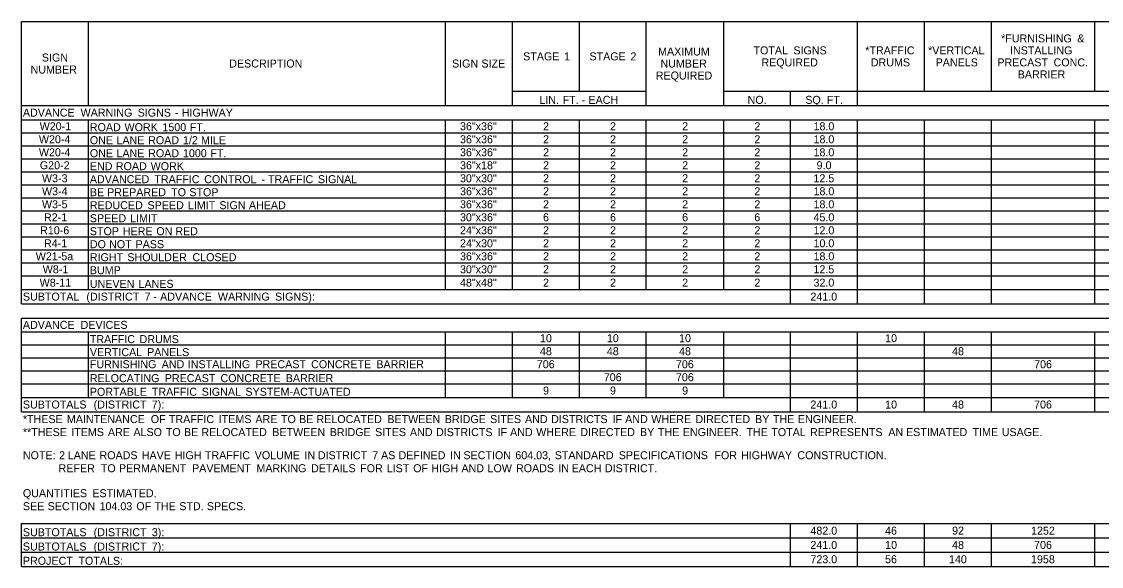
# Model space of a CAD drawing. Extents: x 544478 to 1930787, y -1948294 to 596640.
# Drawn here: x 544484 to 545294, y -1946942 to -1946533 of the extents above; entities that cross this region are included whole.
import ezdxf

# ---------------------------------------------------------------- set-up
doc = ezdxf.new("R2010")
doc.units = 0
doc.layers.add('Default', color=7, linetype='Continuous')

msp = doc.modelspace()

# ---------------------------------------------------------------- linework, layer by layer
at = {"layer": 'Default'}
for p, q in [((544484.28, -1946533.34), (545456.84, -1946533.34)), ((544484.28, -1946744.91), (544484.28, -1946533.34)), ((544484.28, -1946744.91), (544484.28, -1946533.34)), ((544534.49, -1946596.22), (544534.49, -1946533.34)), ((544802.13, -1946596.22), (544802.13, -1946533.34)), ((544852.34, -1946596.22), (544852.34, -1946533.34)), ((544902.55, -1946585.5), (544902.55, -1946533.34)), ((544952.76, -1946596.22), (544952.76, -1946533.34)), ((545010.78, -1946596.22), (545010.78, -1946533.34)), ((545111.2, -1946596.22), (545111.2, -1946533.34)), ((545161.41, -1946585.5), (545161.41, -1946533.34)), ((545211.63, -1946585.5), (545211.63, -1946533.34)), ((545289.14, -1946585.5), (545289.14, -1946533.34)), ((544852.34, -1946585.5), (544952.76, -1946585.5)), ((544952.76, -1946596.22), (544952.76, -1946585.5)), ((545010.78, -1946585.5), (545456.84, -1946585.5)), ((545060.99, -1946596.22), (545060.99, -1946585.5)), ((545111.2, -1946596.22), (545111.2, -1946585.5)), ((544484.28, -1946596.22), (545456.84, -1946596.22)), ((544952.76, -1946596.22), (545456.84, -1946596.22)), ((544484.28, -1946606.95), (545456.84, -1946606.95)), ((544534.49, -1946694.7), (544534.49, -1946606.95)), ((544534.49, -1946734.19), (544534.49, -1946606.95)), ((544802.13, -1946694.7), (544802.13, -1946606.95)), ((544802.13, -1946734.19), (544802.13, -1946606.95)), ((544852.34, -1946694.7), (544852.34, -1946606.95)), ((544852.34, -1946734.19), (544852.34, -1946606.95)), ((544902.55, -1946684.95), (544902.55, -1946606.95)), ((544902.55, -1946734.19), (544902.55, -1946606.95)), ((544952.76, -1946694.7), (544952.76, -1946606.95)), ((544952.76, -1946734.19), (544952.76, -1946606.95)), ((545010.78, -1946734.19), (545010.78, -1946606.95)), ((545060.99, -1946694.7), (545060.99, -1946606.95)), ((545060.99, -1946744.91), (545060.99, -1946606.95)), ((545111.2, -1946694.7), (545111.2, -1946606.95)), ((545111.2, -1946744.91), (545111.2, -1946606.95)), ((545161.41, -1946694.7), (545161.41, -1946606.95)), ((545161.41, -1946744.91), (545161.41, -1946606.95)), ((545211.63, -1946694.7), (545211.63, -1946606.95)), ((545211.63, -1946744.91), (545211.63, -1946606.95)), ((545289.14, -1946694.7), (545289.14, -1946606.95)), ((545289.14, -1946744.91), (545289.14, -1946606.95)), ((544484.28, -1946616.7), (545456.84, -1946616.7)), ((544484.28, -1946626.45), (545456.84, -1946626.45)), ((544484.28, -1946636.2), (545456.84, -1946636.2)), ((544484.28, -1946645.95), (545456.84, -1946645.95)), ((544484.28, -1946655.7), (545456.84, -1946655.7)), ((544484.28, -1946665.45), (545456.84, -1946665.45)), ((544484.28, -1946675.2), (545456.84, -1946675.2)), ((544484.28, -1946684.95), (545456.84, -1946684.95)), ((544484.28, -1946694.7), (545456.84, -1946694.7)), ((544484.28, -1946704.45), (545456.84, -1946704.45)), ((544484.28, -1946714.2), (545456.84, -1946714.2)), ((544484.28, -1946723.95), (545456.84, -1946723.95)), ((544484.28, -1946734.19), (545456.84, -1946734.19)), ((544484.28, -1946734.19), (545456.84, -1946734.19)), ((545111.2, -1946744.91), (545111.2, -1946734.19)), ((545161.41, -1946744.91), (545161.41, -1946734.19)), ((545211.63, -1946744.91), (545211.63, -1946734.19)), ((545289.14, -1946744.91), (545289.14, -1946734.19)), ((544484.28, -1946744.91), (545456.84, -1946744.91)), ((544484.28, -1946755.64), (545456.84, -1946755.64)), ((544484.28, -1946755.64), (545456.84, -1946755.64)), ((544484.28, -1946825.84), (544484.28, -1946755.64)), ((544484.28, -1946825.84), (544484.28, -1946755.64)), ((544484.28, -1946765.87), (545456.84, -1946765.87)), ((544534.49, -1946785.37), (544534.49, -1946765.87)), ((544534.49, -1946815.11), (544534.49, -1946765.87)), ((544802.13, -1946815.11), (544802.13, -1946765.87)), ((544802.13, -1946815.11), (544802.13, -1946765.87)), ((544852.34, -1946815.11), (544852.34, -1946765.87)), ((544852.34, -1946815.11), (544852.34, -1946765.87)), ((544902.55, -1946815.11), (544902.55, -1946765.87)), ((544902.55, -1946815.11), (544902.55, -1946765.87)), ((544952.76, -1946815.11), (544952.76, -1946765.87)), ((544952.76, -1946815.11), (544952.76, -1946765.87)), ((545010.78, -1946815.11), (545010.78, -1946765.87)), ((545060.99, -1946815.11), (545060.99, -1946765.87)), ((545060.99, -1946825.84), (545060.99, -1946765.87)), ((545111.2, -1946765.87), (545161.41, -1946765.87)), ((545111.2, -1946825.84), (545111.2, -1946765.87)), ((545111.2, -1946825.84), (545111.2, -1946765.87)), ((545161.41, -1946825.84), (545161.41, -1946765.87)), ((545161.41, -1946825.84), (545161.41, -1946765.87)), ((545211.63, -1946775.62), (545211.63, -1946765.87)), ((545211.63, -1946825.84), (545211.63, -1946765.87)), ((545289.14, -1946825.84), (545289.14, -1946765.87)), ((545289.14, -1946825.84), (545289.14, -1946765.87)), ((544484.28, -1946775.62), (545211.63, -1946775.62)), ((545211.63, -1946775.62), (545456.84, -1946775.62)), ((544484.28, -1946785.37), (545456.84, -1946785.37)), ((545211.63, -1946825.84), (545211.63, -1946785.37)), ((544484.28, -1946795.12), (544534.49, -1946795.12)), ((544484.28, -1946795.12), (544952.76, -1946795.12)), ((544534.49, -1946815.11), (544534.49, -1946795.12)), ((544802.13, -1946795.12), (544952.76, -1946795.12)), ((544952.76, -1946795.12), (545289.14, -1946795.12)), ((545010.78, -1946795.12), (545211.63, -1946795.12)), ((545211.63, -1946795.12), (545456.84, -1946795.12)), ((544484.28, -1946804.87), (545456.84, -1946804.87)), ((544484.28, -1946815.11), (544534.49, -1946815.11)), ((544484.28, -1946815.11), (545456.84, -1946815.11)), ((544484.28, -1946825.84), (545456.84, -1946825.84)), ((544484.28, -1946909.69), (545456.84, -1946909.69)), ((544484.28, -1946909.69), (545456.84, -1946909.69)), ((544484.28, -1946941.86), (544484.28, -1946909.69)), ((544484.28, -1946941.86), (544484.28, -1946909.69)), ((545060.99, -1946941.86), (545060.99, -1946909.69)), ((545060.99, -1946941.86), (545060.99, -1946909.69)), ((545111.2, -1946941.86), (545111.2, -1946909.69)), ((545161.41, -1946941.86), (545161.41, -1946909.69)), ((545211.63, -1946941.86), (545211.63, -1946909.69)), ((545289.14, -1946941.86), (545289.14, -1946909.69)), ((544484.28, -1946920.41), (545456.84, -1946920.41)), ((544484.28, -1946931.14), (545456.84, -1946931.14)), ((544484.28, -1946941.86), (545456.84, -1946941.86))]:
    msp.add_line(p, q, dxfattribs=at)

# ---------------------------------------------------------------- texts
for s, p in [('*FURNISHING', (545218.8, -1946548.92)), (' &', (545273.72, -1946548.92)), ('SIGN', (544499.47, -1946563.28)), ('STAGE', (544860.4, -1946562.42)), (' 1', (544888.86, -1946562.42)), ('STAGE', (544910.14, -1946562.42)), (' 2', (544938.61, -1946562.42)), ('MAXIMUM', (544961.58, -1946558.78)), ('TOTAL', (545033.14, -1946557.92)), (' SIGNS', (545060.83, -1946557.92)), ('*TRAFFIC', (545116.96, -1946557.92)), ('*VERTICAL', (545164.05, -1946557.92)), ('INSTALLING', (545225.49, -1946557.92)), ('NUMBER', (544491, -1946572.28)), ('DESCRIPTION', (544639.99, -1946567.78)), ('SIGN', (544807.05, -1946567.78)), (' SIZE', (544826.87, -1946567.78)), ('NUMBER', (544963.39, -1946567.78)), ('REQUIRED', (545039.07, -1946566.92)), ('DRUMS', (545121.14, -1946566.92)), ('PANELS', (545169.72, -1946566.92)), ('PRECAST', (545216.05, -1946566.92)), (' CONC.', (545255.94, -1946566.92)), ('REQUIRED', (544959.85, -1946576.78)), ('BARRIER', (545231.3, -1946575.92)), ('LIN.', (544872.51, -1946595.02)), (' FT.', (544887.77, -1946595.02)), (' EACH', (544907.15, -1946595.02)), ('NO.', (545028.72, -1946595.02)), ('SQ.', (545072, -1946595.02)), (' FT.', (545085.87, -1946595.02)), ('ADVANCE', (544485.25, -1946604.59)), (' WARNING', (544526.29, -1946604.59)), (' SIGNS', (544569.09, -1946604.59)), (' HIGHWAY', (544602.16, -1946604.59)), (' -', (544902.09, -1946595.02)), (' -', (544597.1, -1946604.59)), ('W20-1', (544497.81, -1946614.82)), ('ROAD', (544535.46, -1946615.5)), (' WORK', (544559.24, -1946615.5)), (' 1500', (544587.63, -1946615.5)), (' FT.', (544608.19, -1946615.5)), ('36"x36"', (544813.03, -1946614.82)), ('2', (544875.34, -1946614.82)), ('2', (544925.55, -1946614.82)), ('2', (544979.66, -1946614.82)), ('2', (545033.77, -1946614.82)), ('18.0', (545078.14, -1946614.82)), ('W20-4', (544497.24, -1946624.57)), ('ONE', (544535.46, -1946625.25)), (' LANE', (544553.18, -1946625.25)), (' ROAD', (544576.96, -1946625.25)), (' 1/2', (544603.07, -1946625.25)), (' MILE', (544616.6, -1946625.25)), ('36"x36"', (544813.03, -1946624.57)), ('2', (544875.34, -1946624.57)), ('2', (544925.55, -1946624.57)), ('2', (544979.66, -1946624.57)), ('2', (545033.77, -1946624.57)), ('18.0', (545078.14, -1946624.57)), ('W20-4', (544497.24, -1946634.32)), ('ONE', (544535.46, -1946635)), (' LANE', (544553.18, -1946635)), (' ROAD', (544576.96, -1946635)), (' 1000', (544603.07, -1946635)), (' FT.', (544623.63, -1946635)), ('36"x36"', (544813.03, -1946634.32)), ('2', (544875.34, -1946634.32)), ('2', (544925.55, -1946634.32)), ('2', (544979.66, -1946634.32)), ('2', (545033.77, -1946634.32)), ('18.0', (545078.14, -1946634.32)), ('G20-2', (544497.96, -1946644.07)), ('END', (544535.46, -1946644.75)), (' ROAD', (544552.72, -1946644.75)), (' WORK', (544578.82, -1946644.75)), ('36"x18"', (544813.03, -1946644.07)), ('2', (544875.34, -1946644.07)), ('2', (544925.55, -1946644.07)), ('2', (544979.66, -1946644.07)), ('2', (545033.77, -1946644.07)), ('9.0', (545080.47, -1946644.07)), ('W3-3', (544499.56, -1946653.82)), ('ADVANCED', (544535.46, -1946654.5)), (' TRAFFIC', (544581.61, -1946654.5)), (' CONTROL', (544619, -1946654.5)), (' -', (544662.02, -1946654.5)), (' TRAFFIC', (544666.87, -1946654.5)), (' SIGNAL', (544704.26, -1946654.5)), ('30"x30"', (544813.03, -1946653.82)), ('2', (544875.34, -1946653.82)), ('2', (544925.55, -1946653.82)), ('2', (544979.66, -1946653.82)), ('2', (545033.77, -1946653.82)), ('12.5', (545078.11, -1946653.82)), ('W3-4', (544499.57, -1946663.57)), ('BE', (544535.46, -1946664.25)), (' PREPARED', (544546.2, -1946664.25)), (' TO', (544594.21, -1946664.25)), (' STOP', (544607.81, -1946664.25)), ('36"x36"', (544813.03, -1946663.57)), ('2', (544875.34, -1946663.57)), ('2', (544925.55, -1946663.57)), ('2', (544979.66, -1946663.57)), ('2', (545033.77, -1946663.57)), ('18.0', (545078.14, -1946663.57)), ('W3-5', (544499.54, -1946673.32)), ('REDUCED', (544535.46, -1946674)), (' SPEED', (544576.47, -1946674)), (' LIMIT', (544606.78, -1946674)), (' SIGN', (544630.36, -1946674)), (' AHEAD', (544652.5, -1946674)), ('36"x36"', (544813.03, -1946673.32)), ('2', (544875.34, -1946673.32)), ('2', (544925.55, -1946673.32)), ('2', (544979.66, -1946673.32)), ('2', (545033.77, -1946673.32)), ('18.0', (545078.14, -1946673.32)), ('R2-1', (544501.07, -1946683.07)), ('SPEED', (544535.46, -1946683.75)), (' LIMIT', (544563.44, -1946683.75)), ('30"x36"', (544813.03, -1946683.07)), ('6', (544875.3, -1946683.07)), ('6', (544925.52, -1946683.07)), ('6', (544979.63, -1946683.07)), ('6', (545033.74, -1946683.07)), ('45.0', (545078.14, -1946683.07)), ('R10-6', (544498.16, -1946692.82)), ('STOP', (544535.46, -1946693.5)), (' HERE', (544557.93, -1946693.5)), (' ON', (544583.1, -1946693.5)), (' RED', (544597.32, -1946693.5)), ('24"x36"', (544813.03, -1946692.82)), ('2', (544875.34, -1946692.82)), ('2', (544925.55, -1946692.82)), ('2', (544979.66, -1946692.82)), ('2', (545033.77, -1946692.82)), ('12.0', (545078.14, -1946692.82)), ('R4-1', (544501.07, -1946702.57)), ('DO', (544535.46, -1946703.25)), (' NOT', (544547.66, -1946703.25)), (' PASS', (544567.52, -1946703.25)), ('24"x30"', (544813.03, -1946702.57)), ('2', (544875.34, -1946702.57)), ('2', (544925.55, -1946702.57)), ('2', (544979.66, -1946702.57)), ('2', (545033.77, -1946702.57)), ('10.0', (545078.14, -1946702.57)), ('W21-5a', (544494.89, -1946712.32)), ('RIGHT', (544535.46, -1946713)), (' SHOULDER', (544561.37, -1946713)), (' CLOSED', (544610.17, -1946713)), ('36"x36"', (544813.03, -1946712.32)), ('2', (544875.34, -1946712.32)), ('2', (544925.55, -1946712.32)), ('2', (544979.66, -1946712.32)), ('2', (545033.77, -1946712.32)), ('18.0', (545078.14, -1946712.32)), ('W8-1', (544500.14, -1946722.07)), ('BUMP', (544535.46, -1946722.75)), ('30"x30"', (544813.03, -1946722.07)), ('2', (544875.34, -1946722.07)), ('2', (544925.55, -1946722.07)), ('2', (544979.66, -1946722.07)), ('2', (545033.77, -1946722.07)), ('12.5', (545078.11, -1946722.07)), ('W8-11', (544497.81, -1946732.07)), ('UNEVEN', (544535.46, -1946732.99)), (' LANES', (544569.72, -1946732.99)), ('48"x48"', (544813.03, -1946732.07)), ('2', (544875.34, -1946732.07)), ('2', (544925.55, -1946732.07)), ('2', (544979.66, -1946732.07)), ('2', (545033.77, -1946732.07)), ('32.0', (545078.14, -1946732.07)), ('SUBTOTAL', (544485.25, -1946742.55)), (' (DISTRICT', (544530.64, -1946742.55)), (' 7', (544574.24, -1946742.55)), (' ADVANCE', (544585.92, -1946742.55)), (' WARNING', (544629.29, -1946742.55)), (' SIGNS):', (544672.09, -1946742.55)), ('241.0', (545075.82, -1946742.55)), (' -', (544580.86, -1946742.55)), ('ADVANCE', (544485.25, -1946763.75)), (' DEVICES', (544526.29, -1946763.75)), ('TRAFFIC', (544535.46, -1946774.42)), (' DRUMS', (544570.53, -1946774.42)), ('10', (544872.99, -1946773.75)), ('10', (544923.2, -1946773.75)), ('10', (544977.31, -1946773.75)), ('10', (545131.85, -1946773.75)), ('VERTICAL', (544535.46, -1946784.17)), (' PANELS', (544576.16, -1946784.17)), ('48', (544872.97, -1946783.5)), ('48', (544923.18, -1946783.5)), ('48', (544977.29, -1946783.5)), ('48', (545182.04, -1946783.5)), ('FURNISHING', (544535.46, -1946793.25)), (' AND', (544587.1, -1946793.25)), (' INSTALLING', (544606.69, -1946793.25)), (' PRECAST', (544657.4, -1946793.25)), (' CONCRETE', (544699.16, -1946793.25)), (' BARRIER', (544748.09, -1946793.25)), ('706', (544870.64, -1946793.25)), ('706', (544974.97, -1946793.25)), ('706', (545243.58, -1946793.25)), ('RELOCATING', (544535.46, -1946803.67)), (' PRECAST', (544589.44, -1946803.67)), (' CONCRETE', (544631.2, -1946803.67)), (' BARRIER', (544680.13, -1946803.67)), ('706', (544920.86, -1946803)), ('706', (544974.97, -1946803)), ('PORTABLE', (544535.46, -1946813.91)), (' TRAFFIC', (544579.74, -1946813.91)), (' SIGNAL', (544617.13, -1946813.91)), (' SYSTEM-ACTUATED', (544649.92, -1946813.91)), ('9', (544875.3, -1946812.99)), ('9', (544925.51, -1946812.99)), ('9', (544979.62, -1946812.99)), ('SUBTOTALS', (544485.25, -1946823.47)), (' (DISTRICT', (544536.08, -1946823.47)), (' 7):', (544579.68, -1946823.47)), ('241.0', (545075.82, -1946823.47)), ('10', (545131.85, -1946823.47)), ('48', (545182.05, -1946823.47)), ('706', (545243.54, -1946823.47)), ('*THESE', (544485.25, -1946834.39)), (' MAINTENANCE', (544516.02, -1946834.39)), (' OF', (544578.92, -1946834.39)), (' TRAFFIC', (544592.51, -1946834.39)), (' ITEMS', (544629.9, -1946834.39)), (' ARE', (544657.41, -1946834.39)), (' TO', (544676.53, -1946834.39)), (' BE', (544690.12, -1946834.39)), (' RELOCATED', (544703.19, -1946834.39)), (' BETWEEN', (544756.32, -1946834.39)), (' BRIDGE', (544799.42, -1946834.39)), (' SITES', (544833.44, -1946834.39)), (' AND', (544859.56, -1946834.39)), (' DISTRICTS', (544879.14, -1946834.39)), (' IF', (544925.28, -1946834.39)), (' AND', (544934.67, -1946834.39)), (' WHERE', (544954.26, -1946834.39)), (' DIRECTED', (544987.34, -1946834.39)), (' BY', (545032.08, -1946834.39)), (' THE', (545045.53, -1946834.39)), (' ENGINEER.', (545064.18, -1946834.39)), ('**THESE', (544485.25, -1946844.14)), (' ITEMS', (544519.28, -1946844.14)), (' ARE', (544546.79, -1946844.14)), (' ALSO', (544565.91, -1946844.14)), (' TO', (544590.23, -1946844.14)), (' BE', (544603.82, -1946844.14)), (' RELOCATED', (544616.89, -1946844.14)), (' BETWEEN', (544670.02, -1946844.14)), (' BRIDGE', (544713.12, -1946844.14)), (' SITES', (544747.14, -1946844.14)), (' AND', (544773.26, -1946844.14)), (' DISTRICTS', (544792.84, -1946844.14)), (' IF', (544838.98, -1946844.14)), (' AND', (544848.37, -1946844.14)), (' WHERE', (544867.96, -1946844.14)), (' DIRECTED', (544901.04, -1946844.14)), (' BY', (544945.78, -1946844.14)), (' THE', (544959.23, -1946844.14)), (' ENGINEER.', (544977.88, -1946844.14)), (' THE', (545025.59, -1946844.14)), (' TOTAL', (545044.24, -1946844.14)), (' REPRESENTS', (545073.29, -1946844.14)), (' AN', (545132.02, -1946844.14)), (' ESTIMATED', (545145.31, -1946844.14)), (' TIME', (545195.18, -1946844.14)), (' USAGE.', (545217.08, -1946844.14)), ('NOTE:', (544485.25, -1946861.5)), (' 2', (544510.14, -1946861.5)), (' LANE', (544516.68, -1946861.5)), (' ROADS', (544540.46, -1946861.5)), (' HAVE', (544572.17, -1946861.5)), (' HIGH', (544596.88, -1946861.5)), (' TRAFFIC', (544619.49, -1946861.5)), (' VOLUME', (544656.88, -1946861.5)), (' IN', (544694.17, -1946861.5)), (' DISTRICT', (544704.19, -1946861.5)), (' 7', (544745.01, -1946861.5)), (' AS', (544751.61, -1946861.5)), (' DEFINED', (544764.69, -1946861.5)), (' IN', (544803.37, -1946861.5)), (' SECTION', (544813.39, -1946861.5)), (' 604.03,', (544852.3, -1946861.5)), (' STANDARD', (544881.84, -1946861.5)), (' SPECIFICATIONS', (544929.84, -1946861.5)), (' FOR', (545001.61, -1946861.5)), (' HIGHWAY', (545021.52, -1946861.5)), (' CONSTRUCTION.', (545063.84, -1946861.5)), ('            REFER', (544485.25, -1946871.25)), (' TO', (544541.49, -1946871.25)), (' PERMANENT', (544555.08, -1946871.25)), (' PAVEMENT', (544609.88, -1946871.25)), (' MARKING', (544658.17, -1946871.25)), (' DETAILS', (544699.1, -1946871.25)), (' FOR', (544735.93, -1946871.25)), (' LIST', (544755.84, -1946871.25)), (' OF', (544775.7, -1946871.25)), (' HIGH', (544789.29, -1946871.25)), (' AND', (544811.9, -1946871.25)), (' LOW', (544831.48, -1946871.25)), (' ROADS', (544852.81, -1946871.25)), (' IN', (544884.51, -1946871.25)), (' EACH', (544894.54, -1946871.25)), (' DISTRICT.', (544919.48, -1946871.25)), ('QUANTITIES', (544485.25, -1946889.96)), (' ESTIMATED.', (544535.12, -1946889.96)), ('SEE', (544485.25, -1946899.71)), (' SECTION', (544501.58, -1946899.71)), (' 104.03', (544540.49, -1946899.71)), (' OF', (544568.07, -1946899.71)), (' THE', (544581.65, -1946899.71)), (' STD.', (544600.3, -1946899.71)), (' SPECS.', (544621, -1946899.71)), ('SUBTOTALS', (544485.25, -1946919.21)), (' (DISTRICT', (544536.08, -1946919.21)), (' 3):', (544579.68, -1946919.21)), ('482.0', (545075.82, -1946918.05)), ('46', (545131.79, -1946918.05)), ('92', (545182.07, -1946918.05)), ('1252', (545241.27, -1946918.05)), ('241.0', (545075.82, -1946928.77)), ('10', (545131.85, -1946928.77)), ('48', (545182.05, -1946928.77)), ('706', (545243.54, -1946928.77)), ('SUBTOTALS', (544485.25, -1946929.94)), (' (DISTRICT', (544536.08, -1946929.94)), (' 7):', (544579.68, -1946929.94)), ('PROJECT', (544485.25, -1946940.66)), (' TOTALS:', (544524.68, -1946940.66)), ('723.0', (545075.82, -1946939.5)), ('56', (545131.79, -1946939.5)), ('140', (545179.73, -1946939.5)), ('1958', (545241.25, -1946939.5))]:
    msp.add_text(s, height=6, dxfattribs=at).set_placement(p)

doc.saveas('drawing.dxf')
